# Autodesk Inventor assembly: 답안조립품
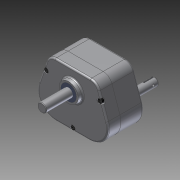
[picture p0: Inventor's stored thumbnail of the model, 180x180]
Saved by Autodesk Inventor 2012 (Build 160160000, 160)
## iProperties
Created: 2014-12
Part Number: 답안조립품
Document SubType Name: Assembly
Designer: Owner
Author: Owner
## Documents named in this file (13)
- C:\Documents and Settings\Owner\바탕 화면\441208V1002\답안조립품.iam
- C:\Documents and Settings\Owner\바탕 화면\441208V1002\1 본체.ipt
- C:\Documents and Settings\Owner\바탕 화면\441208V1002\커버.ipt
- C:\Documents and Settings\Owner\바탕 화면\441208V1002\M 5 x 35.ipt
- C:\Documents and Settings\Owner\바탕 화면\441208V1002\오일시일-D-15.ipt
- C:\Documents and Settings\Owner\바탕 화면\441208V1002\서브축.ipt
- C:\Documents and Settings\Owner\바탕 화면\441208V1002\베어링- 6203.ipt
- C:\Documents and Settings\Owner\바탕 화면\441208V1002\키5x5.ipt
- C:\Documents and Settings\Owner\바탕 화면\441208V1002\서브기어.ipt
- C:\Documents and Settings\Owner\바탕 화면\441208V1002\오일시일-D-17.ipt
- C:\Documents and Settings\Owner\바탕 화면\441208V1002\메인축.ipt
- C:\Documents and Settings\Owner\바탕 화면\441208V1002\메인기어.ipt
- C:\Documents and Settings\Owner\바탕 화면\441208V1002\멈춤링.ipt
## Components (14 placed, 6 different names)
1. 1 본체:1
2. KS B 1003 - 미터 M 5 x 35:1 — 각도:1
3. KS B 1003 - 미터 M 5 x 35:2 — 각도:2
4. KS B 1003 - 미터 M 5 x 35:3 — 각도:3
5. KS B 2804 D D - 15 30 7:1
6. KS B 2804 D D - 15 30 7:2
7. KS B 2023 6203 - 17 x 40 x 12:1
8. KS B 2023 6203 - 17 x 40 x 12:2
9. KS B 2804 D D - 17 30 8:1
10. KS B 2023 6203 - 17 x 40 x 12:3
11. KS B 2023 6203 - 17 x 40 x 12:4
12. KS B 1336 17 x 1:1
13. KS B 1336 17 x 1:2
14. KS B 1336 17 x 1:3
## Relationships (3: Angle 3)
- 각도:1 [Angle]: KS B 1003 - 미터 M 5 x 35:1
- 각도:2 [Angle]: KS B 1003 - 미터 M 5 x 35:2
- 각도:3 [Angle]: KS B 1003 - 미터 M 5 x 35:3
